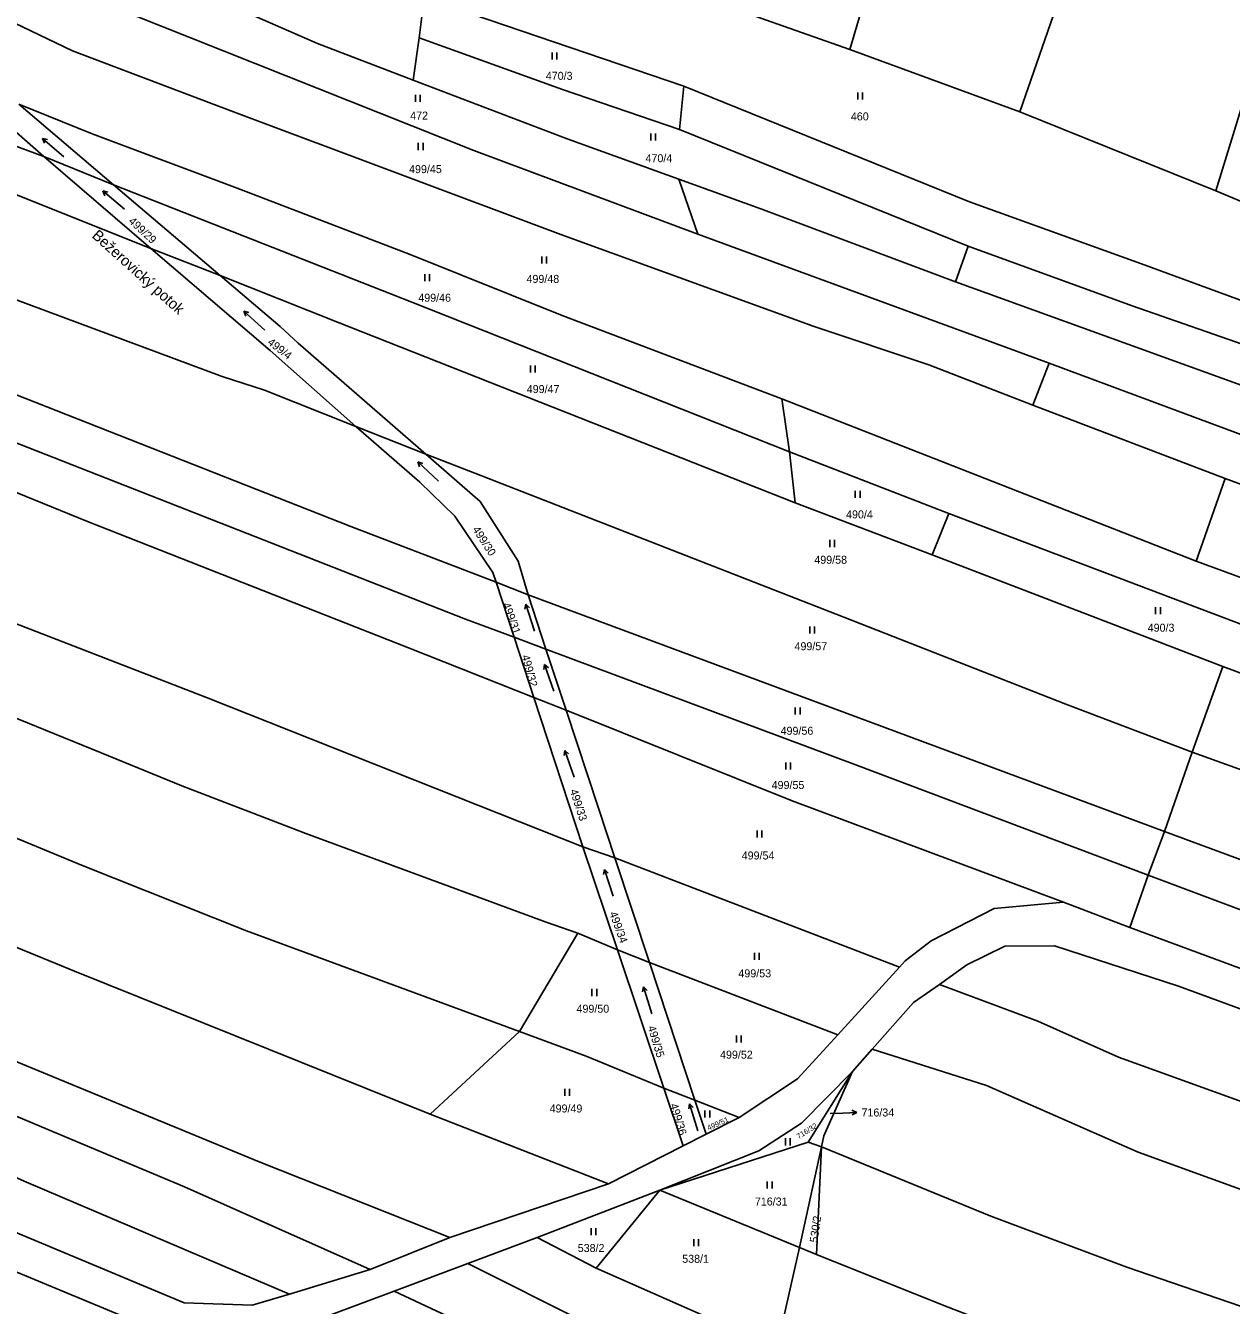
# Model space of a CAD drawing. Extents: x -751333 to -746055, y -1133395 to -1129777.
# Drawn here: x -748441 to -748184.6, y -1130874.9 to -1130603 of the extents above; entities that cross this region are included whole.
import ezdxf

# ---------------------------------------------------------------- set-up
doc = ezdxf.new("R2010")
doc.units = 0
for name, color, linetype in [('Hranice parcel', 7, 'Continuous'), ('Parcelní čísla', 7, 'Continuous'), ('Pop  PČ popisy', 7, 'Continuous'), ('Značky kultur', 7, 'Continuous')]:
    doc.layers.add(name, color=color, linetype=linetype)

msp = doc.modelspace()

# ---------------------------------------------------------------- linework, layer by layer
at = {"layer": 'Hranice parcel'}
for p, q in [((-748306.94, -1130593.5), (-748265.75, -1130608.04)), ((-748357.28, -1130605.56), (-748356.21, -1130597)), ((-748356.21, -1130597), (-748301.06, -1130615.84)), ((-748358.56, -1130614.59), (-748357.28, -1130605.56)), ((-748265.75, -1130608.04), (-748229.57, -1130621.28)), ((-748455.69, -1130614.55), (-748437.09, -1130630.78)), ((-748301.06, -1130615.84), (-748301.92, -1130625.04)), ((-748422.31, -1130636.78), (-748442.43, -1130619.67)), ((-748229.57, -1130621.28), (-748187.91, -1130638.09)), ((-748301.92, -1130625.04), (-748240.56, -1130649.85)), ((-748437.09, -1130630.78), (-748422.31, -1130636.78)), ((-748437.09, -1130630.78), (-748414.36, -1130650.31)), ((-748399.6, -1130656.07), (-748422.31, -1130636.78)), ((-748302.08, -1130635.58), (-748298.06, -1130647.31)), ((-748187.91, -1130638.09), (-748171.3, -1130645.09)), ((-748298.06, -1130647.31), (-748223.38, -1130674.7)), ((-748399.6, -1130656.07), (-748414.36, -1130650.31)), ((-748240.56, -1130649.85), (-748243.24, -1130657.42)), ((-748223.38, -1130674.7), (-748226.83, -1130683.61)), ((-748192.08, -1130716.76), (-748280.18, -1130682.27)), ((-748280.18, -1130682.27), (-748278.6, -1130693.52)), ((-748226.83, -1130683.61), (-748185.93, -1130699.2)), ((-748370.74, -1130688.16), (-748355.87, -1130694.01)), ((-748278.6, -1130693.52), (-748244.7, -1130706.67)), ((-748278.6, -1130693.52), (-748277.39, -1130704.35)), ((-748185.93, -1130699.2), (-748192.08, -1130716.76)), ((-748277.39, -1130704.35), (-748248.26, -1130715.42)), ((-748244.7, -1130706.67), (-748248.26, -1130715.42)), ((-748248.26, -1130715.42), (-748186.46, -1130739.14)), ((-748340.95, -1130721.23), (-748334.14, -1130723.95)), ((-748340.95, -1130721.23), (-748337.1, -1130732.95)), ((-748330.34, -1130735.47), (-748334.14, -1130723.95)), ((-748337.1, -1130732.95), (-748330.34, -1130735.47)), ((-748337.1, -1130732.95), (-748332.9, -1130745.74)), ((-748326.07, -1130748.44), (-748330.34, -1130735.47)), ((-748186.46, -1130739.14), (-748192.95, -1130757.36)), ((-748186.46, -1130739.14), (-748156.81, -1130750.21)), ((-748332.9, -1130745.74), (-748326.07, -1130748.44)), ((-748322.49, -1130777.44), (-748332.9, -1130745.74)), ((-748198.84, -1130774.24), (-748192.95, -1130757.36)), ((-748202.3, -1130783.51), (-748198.84, -1130774.24)), ((-748322.49, -1130777.44), (-748315.72, -1130779.81)), ((-748322.49, -1130777.44), (-748315.11, -1130799.35)), ((-748308.36, -1130802.04), (-748315.72, -1130779.81)), ((-748255.16, -1130803.06), (-748315.72, -1130779.81)), ((-748206.22, -1130794.61), (-748202.3, -1130783.51)), ((-748206.22, -1130794.61), (-748220.29, -1130789.23)), ((-748323.6, -1130795.85), (-748336, -1130816.73)), ((-748323.6, -1130795.85), (-748315.11, -1130799.35)), ((-748315.11, -1130799.35), (-748308.36, -1130802.04)), ((-748315.11, -1130799.35), (-748305.32, -1130828.72)), ((-748298.68, -1130831.28), (-748308.36, -1130802.04)), ((-748268.27, -1130817.4), (-748308.36, -1130802.04)), ((-748255.16, -1130803.06), (-748268.27, -1130817.4)), ((-748336, -1130816.73), (-748354.99, -1130834.29)), ((-748260.98, -1130820.46), (-748265.19, -1130825.19)), ((-748274.62, -1130840.2), (-748265.19, -1130825.19)), ((-748305.32, -1130828.72), (-748298.68, -1130831.28)), ((-748305.32, -1130828.72), (-748301.18, -1130841.02)), ((-748296.28, -1130838.54), (-748298.68, -1130831.28)), ((-748289.25, -1130834.98), (-748298.68, -1130831.28)), ((-748354.99, -1130834.29), (-748317.07, -1130849.07)), ((-748289.25, -1130834.98), (-748296.28, -1130838.54)), ((-748296.28, -1130838.54), (-748301.18, -1130841.02)), ((-748301.18, -1130841.02), (-748317.07, -1130849.07)), ((-748274.62, -1130840.2), (-748306.12, -1130850.42)), ((-748271.76, -1130841.22), (-748276.46, -1130862.6)), ((-748271.76, -1130841.22), (-748274.62, -1130840.2)), ((-748272.8, -1130864.07), (-748271.76, -1130841.22)), ((-748317.07, -1130849.07), (-748350.77, -1130860.5)), ((-748332.19, -1130860.47), (-748306.12, -1130850.42)), ((-748306.12, -1130850.42), (-748319.69, -1130866.98)), ((-748276.46, -1130862.6), (-748306.12, -1130850.42)), ((-748350.77, -1130860.5), (-748367.71, -1130867.32)), ((-748346.93, -1130865.99), (-748332.19, -1130860.47)), ((-748319.69, -1130866.98), (-748332.19, -1130860.47)), ((-748276.46, -1130862.6), (-748281.3, -1130883.89)), ((-748276.46, -1130862.6), (-748272.8, -1130864.07)), ((-748362.61, -1130871.86), (-748346.93, -1130865.99)), ((-748367.71, -1130867.32), (-748384.89, -1130872.51)), ((-748281.3, -1130883.89), (-748319.69, -1130866.98)), ((-748379.12, -1130878.04), (-748362.61, -1130871.86))]:
    msp.add_line(p, q, dxfattribs=at)
for points in [[(-748265.75, -1130608.04), (-748247.9, -1130547.61), (-748233.17, -1130503.73)], [(-748229.57, -1130621.28), (-748216.56, -1130583.68), (-748204.16, -1130547.99), (-748197.06, -1130528.56)], [(-748187.91, -1130638.09), (-748178.92, -1130608.81), (-748161.77, -1130554.58)], [(-748485.04, -1130582.73), (-748469.61, -1130589.74), (-748431.04, -1130608.33), (-748396.79, -1130621.28), (-748326.64, -1130647.59), (-748273.31, -1130666.87), (-748248.94, -1130675.02), (-748226.83, -1130683.61)], [(-748400.65, -1130597.24), (-748378.93, -1130606.77), (-748358.56, -1130614.59)], [(-748418.92, -1130600.37), (-748345.69, -1130629.51), (-748298.06, -1130647.31)], [(-748370.74, -1130688.16), (-748390.16, -1130680.44), (-748399.18, -1130677.54), (-748453.71, -1130657.26), (-748528.86, -1130627.98), (-748582.3, -1130606.18)], [(-748357.28, -1130605.56), (-748326.8, -1130616.53), (-748301.92, -1130625.04)], [(-748474.99, -1130628.2), (-748478.16, -1130615.62), (-748437.09, -1130630.78)], [(-748358.56, -1130614.59), (-748325.84, -1130627.02), (-748302.08, -1130635.58)], [(-748301.06, -1130615.84), (-748240.31, -1130640.44), (-748203.71, -1130653.58), (-748161.84, -1130668.98)], [(-748280.18, -1130682.27), (-748326.88, -1130664.57), (-748359.23, -1130651.59), (-748396.02, -1130637.54), (-748426.83, -1130625.94), (-748442.43, -1130619.67)], [(-748340.95, -1130721.23), (-748371.81, -1130709.41), (-748485.85, -1130664.58), (-748534.39, -1130645.25), (-748586.34, -1130622.61)], [(-748414.36, -1130650.31), (-748452.93, -1130634.95), (-748474.99, -1130628.2)], [(-748337.1, -1130732.95), (-748347.47, -1130729.08), (-748459.12, -1130685.32), (-748534.17, -1130654.92), (-748588.68, -1130630.55)], [(-748422.31, -1130636.78), (-748358.85, -1130661.76), (-748278.6, -1130693.52)], [(-748302.08, -1130635.58), (-748284.66, -1130641.91), (-748243.24, -1130657.42)], [(-748332.9, -1130745.74), (-748359.6, -1130735.19), (-748427.81, -1130708.36), (-748542.83, -1130661.55), (-748593.74, -1130637.98)], [(-748414.36, -1130650.31), (-748389.01, -1130672.04), (-748370.74, -1130688.16)], [(-748240.56, -1130649.85), (-748205.74, -1130662.52), (-748166.46, -1130676.19), (-748149.75, -1130682.7), (-748123.01, -1130692.38), (-748074.3, -1130710.72), (-748054.6, -1130717.75), (-748018.25, -1130732.85), (-747986.44, -1130749.26)], [(-748399.6, -1130656.07), (-748374.67, -1130665.95), (-748277.39, -1130704.35)], [(-748355.87, -1130694.01), (-748383.04, -1130670.46), (-748386.85, -1130666.91), (-748399.6, -1130656.07)], [(-748243.24, -1130657.42), (-748166.65, -1130685.11), (-748094.37, -1130712.93), (-748058.72, -1130726.42), (-748019.1, -1130743.55), (-747990.16, -1130757.72)], [(-748606.79, -1130664), (-748593.41, -1130669.82), (-748555.79, -1130686.41), (-748521.14, -1130699.97), (-748463.67, -1130722.09), (-748402.55, -1130745.71), (-748322.49, -1130777.44)], [(-748223.38, -1130674.7), (-748160.68, -1130697.99), (-748104.99, -1130718.13), (-748087.93, -1130725.07), (-748056.46, -1130736.89), (-748027.2, -1130749.04), (-747994, -1130766.24)], [(-748370.74, -1130688.16), (-748357.13, -1130699.98), (-748349.74, -1130707.22), (-748341.63, -1130719.17), (-748340.95, -1130721.23)], [(-748591.33, -1130689.59), (-748556.18, -1130705.09), (-748511.54, -1130723.13), (-748468.11, -1130739.92), (-748424.93, -1130757.48), (-748407.79, -1130764.49), (-748381.4, -1130774.63), (-748330.32, -1130793.51), (-748323.6, -1130795.85)], [(-748334.14, -1130723.95), (-748336.28, -1130716.76), (-748344.32, -1130704.11), (-748355.87, -1130694.01)], [(-748192.95, -1130757.36), (-748219.82, -1130747.15), (-748267.04, -1130728.69), (-748344.18, -1130698.6), (-748355.87, -1130694.01)], [(-748185.93, -1130699.2), (-748116.35, -1130724.81), (-748065.1, -1130743.37), (-748028.39, -1130758.32), (-747998.62, -1130776.08)], [(-748244.7, -1130706.67), (-748172.71, -1130733.91), (-748157.04, -1130739.82)], [(-748600.62, -1130708.93), (-748572.02, -1130722.05), (-748553.57, -1130730.11), (-748529.63, -1130739.69), (-748429.06, -1130781.38), (-748394.01, -1130795.35), (-748336, -1130816.73)], [(-748192.08, -1130716.76), (-748141.67, -1130735.26), (-748110.72, -1130746.5), (-748083.73, -1130756.86), (-748044.13, -1130772.48), (-748036.15, -1130775.89), (-748006.3, -1130791.42)], [(-748198.84, -1130774.24), (-748264.42, -1130749.83), (-748334.14, -1130723.95)], [(-748609.37, -1130729.04), (-748586.47, -1130739.97), (-748565.25, -1130748.92), (-748478.86, -1130784.11), (-748430.59, -1130803.91), (-748354.99, -1130834.29)], [(-748202.3, -1130783.51), (-748264.68, -1130759.98), (-748330.34, -1130735.47)], [(-748617.75, -1130748.36), (-748594.66, -1130762.19), (-748574.85, -1130769.98), (-748508.41, -1130796.48), (-748448.56, -1130820.81), (-748391.34, -1130844.41), (-748350.77, -1130860.5)], [(-748315.72, -1130779.81), (-748319.21, -1130769.27), (-748326.07, -1130748.44)], [(-748220.29, -1130789.23), (-748278.03, -1130767.72), (-748326.07, -1130748.44)], [(-748638.72, -1130751.72), (-748602.16, -1130770.3), (-748522.97, -1130802.41), (-748472.42, -1130822.39), (-748429.14, -1130840.54), (-748407.16, -1130849.74), (-748367.71, -1130867.32)], [(-748192.95, -1130757.36), (-748149.26, -1130773.11), (-748117.42, -1130785.04), (-748079.7, -1130799.19), (-748023.6, -1130824.38)], [(-748641.83, -1130766.14), (-748594.17, -1130785.58), (-748542.67, -1130805.9), (-748476.15, -1130833.14), (-748440.81, -1130848.76), (-748384.89, -1130872.51)], [(-748384.89, -1130872.51), (-748392.79, -1130874.89), (-748407.29, -1130874.39), (-748504.41, -1130833.78), (-748556.44, -1130811.2), (-748636.94, -1130777.36), (-748641.83, -1130766.14)], [(-748198.84, -1130774.24), (-748124.83, -1130801.55), (-748095.68, -1130812.38), (-748052.4, -1130830.31), (-748030.93, -1130840.93)], [(-748202.3, -1130783.51), (-748146.21, -1130804.55), (-748090.95, -1130825.26), (-748056.18, -1130839.2), (-748035.09, -1130849.72)], [(-748640.02, -1130785.32), (-748543.51, -1130825.81), (-748464.71, -1130858.77), (-748407.23, -1130882.69)], [(-748220.29, -1130789.23), (-748235.03, -1130790.57), (-748248.44, -1130797.43), (-748253.94, -1130801.72), (-748255.16, -1130803.06)], [(-748042.25, -1130857.8), (-748097.77, -1130834.89), (-748116.18, -1130827.89), (-748206.22, -1130794.61)], [(-748246.71, -1130806.7), (-748240.86, -1130802.57), (-748232.82, -1130798.59), (-748222.25, -1130798.5), (-748195.87, -1130807.09), (-748171.55, -1130816.01), (-748091.95, -1130844.69), (-748061.9, -1130856.72), (-748042.73, -1130867.52)], [(-748260.98, -1130820.46), (-748252.18, -1130810.57), (-748246.71, -1130806.7)], [(-748037.84, -1130894.2), (-748054.55, -1130885.78), (-748102.13, -1130862.63), (-748153.66, -1130841.78), (-748178, -1130833.24), (-748208.63, -1130822.17), (-748225.74, -1130814.53), (-748246.71, -1130806.7)], [(-748305.32, -1130828.72), (-748321.79, -1130821.98), (-748336, -1130816.73)], [(-748268.27, -1130817.4), (-748276.84, -1130826.78), (-748289.25, -1130834.98)], [(-748027.06, -1130916.24), (-748075.79, -1130892.9), (-748112.36, -1130877.79), (-748129.42, -1130870.81), (-748173.97, -1130853.4), (-748204.44, -1130842.38), (-748236.71, -1130828.16), (-748260.98, -1130820.46)], [(-748306.12, -1130850.42), (-748285.08, -1130842.06), (-748276.01, -1130836.18), (-748265.19, -1130825.19)], [(-748265.19, -1130825.19), (-748271.25, -1130838.88), (-748271.76, -1130841.22)], [(-748271.76, -1130841.22), (-748235.77, -1130855.93), (-748206.84, -1130866.81), (-748165.74, -1130880.87), (-748130.12, -1130894.99), (-748094.02, -1130910.31), (-748045.92, -1130930.72), (-748002.03, -1130951.62), (-747975.69, -1130968.08), (-747956.74, -1130979.41)], [(-748283.22, -1130895.4), (-748321.83, -1130878.64), (-748346.93, -1130865.99)], [(-747973.45, -1130994.17), (-747986.3, -1130986.83), (-748025.01, -1130962.88), (-748060.2, -1130946.83), (-748098.9, -1130931.91), (-748130.17, -1130918.61), (-748198.42, -1130893.2), (-748245.75, -1130874.96), (-748272.8, -1130864.07)], [(-748285.26, -1130906.35), (-748321.46, -1130891.15), (-748362.61, -1130871.86)]]:
    msp.add_lwpolyline(points, dxfattribs=at)
at = {"layer": 'Pop  PČ popisy'}
for p, q in [((-748269.9, -1130834.17), (-748267.26, -1130834.05)), ((-748267.26, -1130834.05), (-748264.263, -1130833.893)), ((-748264.263, -1130833.893), (-748265.289, -1130833.445)), ((-748264.263, -1130833.893), (-748265.237, -1130834.445))]:
    msp.add_line(p, q, dxfattribs=at)
at = {"layer": 'Značky kultur'}
for p, q in [((-748329.001, -1130610.17), (-748329.001, -1130608.67)), ((-748328, -1130610.17), (-748328, -1130608.67)), ((-748358.111, -1130619.19), (-748358.111, -1130617.69)), ((-748357.11, -1130619.19), (-748357.11, -1130617.69)), ((-748264.031, -1130618.7), (-748264.031, -1130617.2)), ((-748263.03, -1130618.7), (-748263.03, -1130617.2)), ((-748308.081, -1130627.38), (-748308.081, -1130625.88)), ((-748307.08, -1130627.38), (-748307.08, -1130625.88)), ((-748432.863, -1130630.87), (-748437.391, -1130626.934)), ((-748437.391, -1130626.934), (-748436.983, -1130627.954)), ((-748437.391, -1130626.934), (-748436.325, -1130627.197)), ((-748357.481, -1130629.4), (-748357.481, -1130627.9)), ((-748356.48, -1130629.4), (-748356.48, -1130627.9)), ((-748419.959, -1130641.961), (-748424.556, -1130638.104)), ((-748424.556, -1130638.104), (-748424.13, -1130639.116)), ((-748424.556, -1130638.104), (-748423.485, -1130638.348)), ((-748331.231, -1130653.52), (-748331.231, -1130652.02)), ((-748330.23, -1130653.52), (-748330.23, -1130652.02)), ((-748356.101, -1130657.3), (-748356.101, -1130655.8)), ((-748355.1, -1130657.3), (-748355.1, -1130655.8)), ((-748390.118, -1130667.69), (-748394.576, -1130663.675)), ((-748394.576, -1130663.675), (-748394.186, -1130664.701)), ((-748394.576, -1130663.675), (-748393.515, -1130663.956)), ((-748333.621, -1130676.71), (-748333.621, -1130675.21)), ((-748332.62, -1130676.71), (-748332.62, -1130675.21)), ((-748353.203, -1130699.788), (-748357.591, -1130695.696)), ((-748357.591, -1130695.696), (-748357.218, -1130696.729)), ((-748357.591, -1130695.696), (-748356.534, -1130695.996)), ((-748264.571, -1130703.34), (-748264.571, -1130701.84)), ((-748263.57, -1130703.34), (-748263.57, -1130701.84)), ((-748270.001, -1130713.77), (-748270.001, -1130712.27)), ((-748269, -1130713.77), (-748269, -1130712.27)), ((-748334.654, -1130725.918), (-748334.829, -1130727.002)), ((-748332.8, -1130731.624), (-748334.654, -1130725.918)), ((-748334.654, -1130725.918), (-748333.875, -1130726.692)), ((-748200.721, -1130728.01), (-748200.721, -1130726.51)), ((-748199.72, -1130728.01), (-748199.72, -1130726.51)), ((-748274.271, -1130732.14), (-748274.271, -1130730.64)), ((-748273.27, -1130732.14), (-748273.27, -1130730.64)), ((-748330.624, -1130738.694), (-748330.78, -1130739.782)), ((-748328.671, -1130744.368), (-748330.624, -1130738.694)), ((-748330.624, -1130738.694), (-748329.832, -1130739.455)), ((-748277.331, -1130749.33), (-748277.331, -1130747.83)), ((-748276.33, -1130749.33), (-748276.33, -1130747.83)), ((-748326.334, -1130756.984), (-748326.49, -1130758.072)), ((-748324.381, -1130762.658), (-748326.334, -1130756.984)), ((-748326.334, -1130756.984), (-748325.542, -1130757.745)), ((-748279.341, -1130761.04), (-748279.341, -1130759.54)), ((-748278.34, -1130761.04), (-748278.34, -1130759.54)), ((-748285.461, -1130775.52), (-748285.461, -1130774.02)), ((-748284.46, -1130775.52), (-748284.46, -1130774.02)), ((-748317.934, -1130782.268), (-748318.109, -1130783.352)), ((-748316.08, -1130787.974), (-748317.934, -1130782.268)), ((-748317.934, -1130782.268), (-748317.155, -1130783.042)), ((-748286.011, -1130801.5), (-748286.011, -1130800)), ((-748285.01, -1130801.5), (-748285.01, -1130800)), ((-748320.561, -1130809.17), (-748320.561, -1130807.67)), ((-748319.56, -1130809.17), (-748319.56, -1130807.67)), ((-748309.594, -1130807.232), (-748309.788, -1130808.313)), ((-748307.84, -1130812.97), (-748309.594, -1130807.232)), ((-748309.594, -1130807.232), (-748308.829, -1130808.02)), ((-748289.811, -1130819.04), (-748289.811, -1130817.54)), ((-748288.81, -1130819.04), (-748288.81, -1130817.54)), ((-748326.341, -1130830.37), (-748326.341, -1130828.87)), ((-748325.34, -1130830.37), (-748325.34, -1130828.87)), ((-748299.794, -1130832.072), (-748299.988, -1130833.153)), ((-748298.04, -1130837.81), (-748299.794, -1130832.072)), ((-748299.794, -1130832.072), (-748299.029, -1130832.86)), ((-748296.541, -1130835), (-748296.541, -1130833.5)), ((-748295.54, -1130835), (-748295.54, -1130833.5)), ((-748279.431, -1130840.91), (-748279.431, -1130839.41)), ((-748278.43, -1130840.91), (-748278.43, -1130839.41)), ((-748283.281, -1130850.08), (-748283.281, -1130848.58)), ((-748282.28, -1130850.08), (-748282.28, -1130848.58)), ((-748320.761, -1130860.02), (-748320.761, -1130858.52)), ((-748319.76, -1130860.02), (-748319.76, -1130858.52)), ((-748298.921, -1130862.31), (-748298.921, -1130860.81)), ((-748297.92, -1130862.31), (-748297.92, -1130860.81))]:
    msp.add_line(p, q, dxfattribs=at)

# ---------------------------------------------------------------- texts
at = {"layer": 'Parcelní čísla'}
for s, p in [('470/3', (-748330.38, -1130614.49)), ('472', (-748359.21, -1130622.94)), ('460', (-748265.52, -1130623.11)), ('470/4', (-748309.18, -1130632)), ('499/45', (-748359.45, -1130634.31)), ('499/48', (-748334.48, -1130657.64)), ('499/46', (-748357.49, -1130661.64)), ('499/47', (-748334.43, -1130681.05)), ('490/4', (-748266.54, -1130707.68)), ('499/58', (-748273.29, -1130717.32)), ('490/3', (-748202.41, -1130731.76)), ('499/57', (-748277.5, -1130735.69)), ('499/56', (-748280.46, -1130753.66)), ('499/55', (-748282.36, -1130765.18)), ('499/54', (-748288.73, -1130780.16)), ('499/53', (-748289.43, -1130805.2)), ('499/50', (-748323.85, -1130812.72)), ('499/52', (-748293.33, -1130822.48)), ('499/49', (-748329.56, -1130833.92)), ('716/34', (-748263.26, -1130834.77)), ('716/31', (-748285.93, -1130853.69)), ('538/2', (-748323.59, -1130863.57)), ('538/1', (-748301.38, -1130865.86))]:
    msp.add_text(s, height=1.7, dxfattribs=at).set_placement(p)
for s, height, rotation, p in [('499/29', 1.7, 317, (-748419.219, -1130644.711)), ('499/4', 1.7, 322, (-748389.693, -1130670.539)), ('499/30', 1.7, 303, (-748346.062, -1130710.032)), ('499/31', 1.7, 290, (-748339.618, -1130725.92)), ('499/32', 1.7, 285, (-748335.531, -1130736.919)), ('499/33', 1.7, 288, (-748325.288, -1130765.522)), ('499/34', 1.7, 290, (-748316.888, -1130791.58)), ('499/35', 1.7, 287, (-748308.742, -1130815.758)), ('499/36', 1.7, 287, (-748304.012, -1130832.278)), ('499/51', 1.14, 24, (-748295.768, -1130837.79)), ('716/32', 1.14, 32, (-748276.617, -1130839.603)), ('530/2', 1.7, 82, (-748272.618, -1130861.648))]:
    msp.add_text(s, height=height, rotation=rotation, dxfattribs=at).set_placement(p)
at = {"layer": 'Pop  PČ popisy'}
msp.add_text('Bežerovický potok', height=2.3, rotation=318, dxfattribs=at).set_placement((-748427.035, -1130647.823))

doc.saveas('drawing.dxf')
